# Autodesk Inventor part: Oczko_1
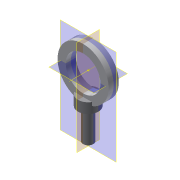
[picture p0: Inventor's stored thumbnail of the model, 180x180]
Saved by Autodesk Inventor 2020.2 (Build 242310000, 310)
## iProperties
Created: 2014-08
Part Number: Oczko_1
Material: Ogólny
Document SubType Name: Modeling
Designer: F.Stasiak
Density: 1 g/cm^3
Appearance: Domyślna
Catalog Web Link: www.expertbooks.pl
Manager: www.cadconsulting.pl
Company: Fabian Stasiak CAD Consulting
Author: F.Stasiak
Subject: Zbiór ćwiczeń. Autodesk Inventor 2020. Kurs Professional
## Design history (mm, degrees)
sketch "Szkic1"
  geometry: C1 r 2.5 at (0, 0); 1 further point
  constraints: 1 centre point, 1 coincident
  dimensions: "d0" = 5 diameter of C1
extrude "Wyciągnięcie proste1" new body sketch "Szkic1" distance "d1" = 20; taper "d2" = 0 deg
sketch "Szkic3"
  geometry: C1 r 5 at (0, 0); 1 further point
  constraints: 1 centre point, 1 coincident
  dimensions: "d5" = 10 diameter of C1
extrude "Wyciągnięcie proste2" join sketch "Szkic3" distance "d6" = 5; taper "d7" = 0 deg
sketch "Szkic2"
  geometry: L1 (2.5, 20)-(-2.5, 20) reference; L2 (-5, 15)-(5, 15) reference; C1 r 8.5 at (0, 30); C2 r 12.5 at (0, 30); 1 further point
  constraints: 2 centre point, 1 coincident
  dimensions: "d3" = 17 diameter of C1; "d4" = 25 diameter of C2; "d8" = 15 distance from line of C1.centre L2
extrude "Wyciągnięcie proste3" join sketch "Szkic2" stored distance "d9" = 5; taper "d10" = 0 deg
node "Punkt konstrukcyjny1"
  node "Płaszczyzna konstrukcyjna1"
node "Bryła1"
node "Oś konstrukcyjna1"
other parameters: "d11" = 90 deg
